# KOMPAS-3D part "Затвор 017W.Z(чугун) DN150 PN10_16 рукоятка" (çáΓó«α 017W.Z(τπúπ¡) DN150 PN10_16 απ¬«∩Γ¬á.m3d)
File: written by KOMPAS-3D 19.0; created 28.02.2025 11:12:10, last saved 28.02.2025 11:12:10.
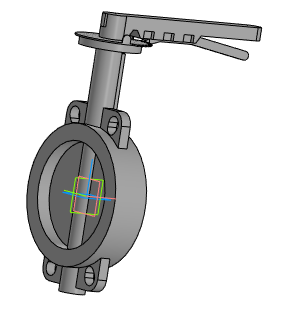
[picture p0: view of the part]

Document properties: Автор: Евгений; Полное имя файла: Затвор 017W.Z(чугун) DN150 PN10_16 рукоятка.a3d

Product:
- Part/product: Затвор 017W.Z(чугун) DN150 PN10_16 рукоятка
    Масса: 19.6542

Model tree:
1. Операция без истории:1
